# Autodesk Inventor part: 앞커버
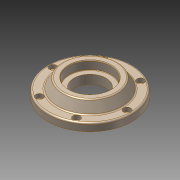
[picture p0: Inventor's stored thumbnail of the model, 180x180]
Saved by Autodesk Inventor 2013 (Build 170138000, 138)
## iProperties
Created: 2013-01
Part Number: 앞커버
Document SubType Name: Modeling
Designer: 한국산업디자인학원[gmhk.co.kr]
Density: 2.71 g/cm^3
Material: 알루미늄 6061
Mass: 415.969 g
Surface Area: 272.105 cm^2
Volume: 153.494 cm^3
Author: 한국산업디자인학원[gmhk.co.kr]
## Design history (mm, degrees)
sketch "스케치2"
  geometry: L1 (-55, 0)-(55, 0) reference; L2 (35.98, -6)-(-35.98, -6) reference; L3 (-42.5, -25)-(-42.5, 0) reference; L4 (-37, -6)-(-37, 0); L5 (-55, 0)-(-55, 10); L6 (-55, 10)-(-42.5, 10); L7 (-37, -6)-(-42.5, -6); L8 (-42.5, 10)-(-34.994, 23); L9 (-34.994, 23)-(0, 23); L10 (-55, 0)-(-42.5, 0); L11 (-42.5, -6)-(-42.5, 0); L12 (0, 0)-(0, 23); L13 (0, 0)-(-37, 0)
  constraints: 22 end point, 4 perpendicular, 3 collinear, 2 parallel, 2 point on line, 1 vertical, 2 other
  dimensions: "d2" = 10 distance of L1.start L5.end; "d4" = 120 deg angle of L8 L6; "d5" = 13 distance between parallel lines of L6 L9; "d6" = 74 diameter of L4 L12; "d7" = 85 diameter of L6.end L12
revolve "회전1" sketch "스케치2" stored, may be unused: angle "d8" = 90 deg
fillet "모깎기1" dims "d9" = 2
sketch "스케치3"
  geometry: C1 r 2.067 at (48.5, 0) reference; 1 further point
hole "구멍1" sketch "스케치3" at (48.5, 0) diameter "d10" = 5.5; stored, may be unused: countersink angle "d14" = 90 deg, drill point angle "d16" = 118 deg; dims "d11" = 6, "d12" = 9.5, "d13" = 5.4, "d15" = 8
fillet "모깎기2" dims "d20" = 3
chamfer "모따기1" distance "d21" = 1; stored, may be unused: second distance "d22" = 2, angle "d23" = 45 deg
sketch "스케치4"
  geometry: L1 (-33.84, 23)-(33.84, 23) reference; L2 (34, 0)-(-34, 0) reference; L3 (0, 0)-(0, 23); L4 (27.5, 21.9)-(27.5, 12.1); L5 (27, 11.6)-(21, 11.6); L6 (21, 11.6)-(21, 0); L7 (27.5, 21.9)-(28.135, 23); A1 r 0.5 centre (27, 12.1) between (27, 11.6) and (27.5, 12.1)
  constraints: 10 end point, 2 perpendicular, 2 point on circle, 2 point on line, 2 tangent, 1 centre point, 1 midpoint, 1 parallel
  dimensions: "d24" = 11.4 distance between parallel lines of L5 L1; "d25" = 1.1 distance from line of L4.start L1; "d26" = 30 deg angle of L7 L4; "d27" = 0.5 radius of A1; "d28" = 55 diameter of L4 L3; "d29" = 42 diameter of L6 L3
revolve "회전2" sketch "스케치4" stored, may be unused: angle "d30" = 90 deg
node "솔리드1"
pattern_circular "원형 패턴1" dims angle "d18" = 360 deg
node "참조1"
node "참조2"
node "참조3"
